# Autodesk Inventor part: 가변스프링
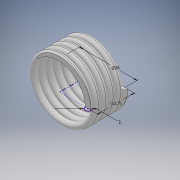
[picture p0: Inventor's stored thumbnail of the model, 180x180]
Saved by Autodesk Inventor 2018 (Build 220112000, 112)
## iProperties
Created: 2020-06
Part Number: 가변스프링
Material: 일반
Document SubType Name: Modeling
Designer: USER
Density: 1 g/cm^3
Appearance: 기본값
Mass: 0.954704 g
Surface Area: 19.5546 cm^2
Volume: 0.954704 cm^3
Author: USER
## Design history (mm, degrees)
sketch "스케치1"
  geometry: L1 (0, 0)-(10, 0); L2 (10, 0)-(10, 12.7); L3 (10, 12.7)-(0, 12.7); L4 (0, 12.7)-(0, 0); C1 r 1 at (10, 0)
  constraints: 8 end point, 2 parallel, 1 centre point, 1 coincident, 1 horizontal, 1 perpendicular
  dimensions: "d1" = 12.7 distance of L2.end L1.end (derived); "d2" = 2 diameter of C1; "d15" = 20 diameter of L2 L4
feature "코일1" sketch "스케치1" pitch "d3" = 10; turns "d5" = 5; dims "d4" = 12.7 (= d1), "d6" = 0, angle "d7" = 90 deg, angle "d8" = 90 deg, "d9" = 0, "d10" = 0
sketch "스케치2"
  geometry: L1 (-9, 0)-(-11, 0) reference; 1 further point
  constraints: 1 horizontal alignment
extrude "돌출1" cut sketch "스케치2" extent not by distance; stored distance "d11" = 10; taper "d12" = 0 deg
node "작업 평면1"
sketch "스케치3"
  geometry: L1 (9, 0)-(11, 0) reference; 2 further points
  constraints: 1 other
extrude "돌출2" cut sketch "스케치3" extent not by distance; stored distance "d13" = 10; taper "d14" = 0 deg
node "솔리드1"
node "절단 모서리 투영1"
node "절단 모서리 투영2"
